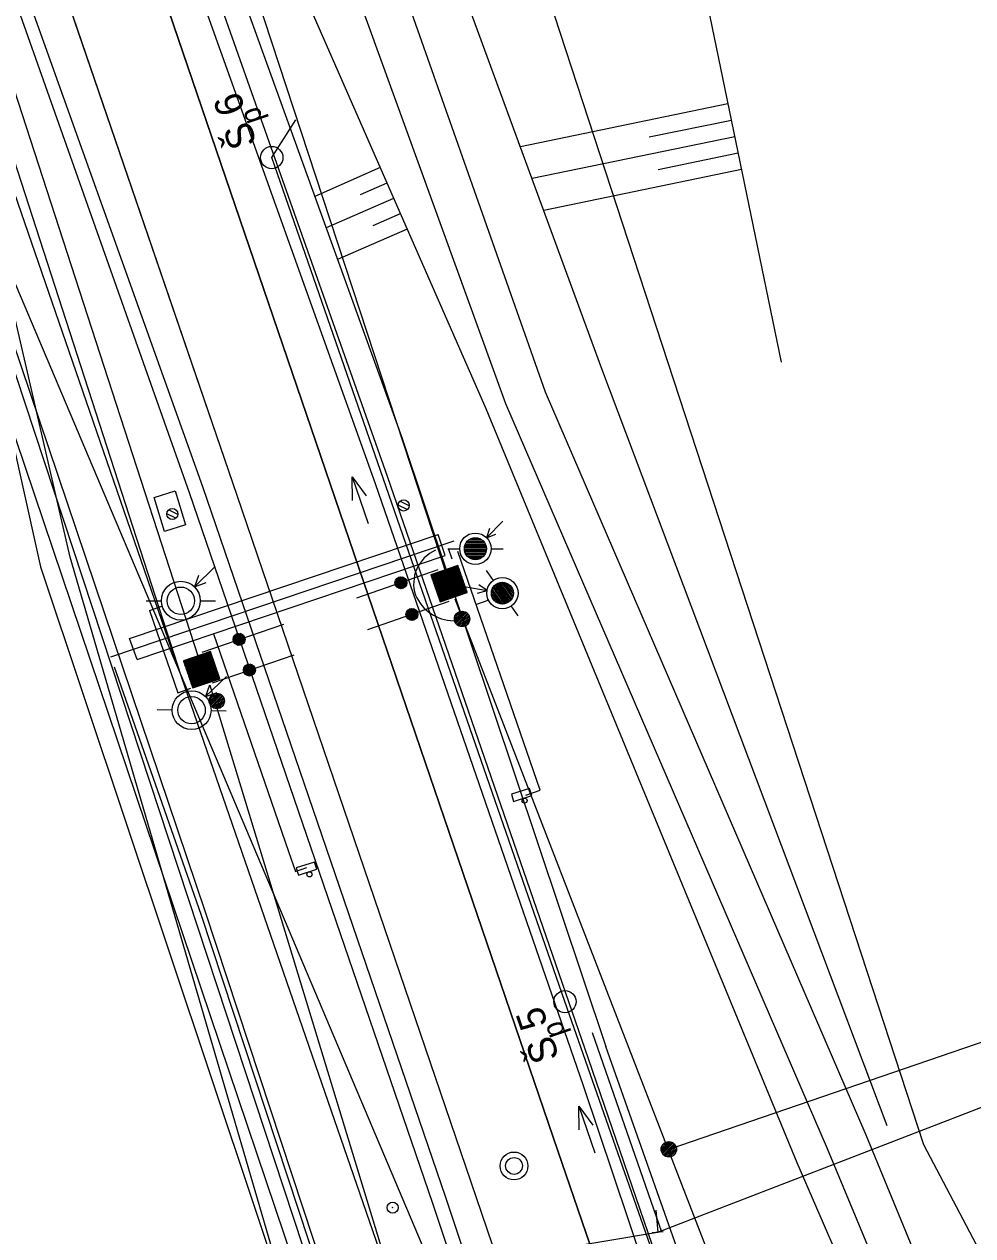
# Model space of a CAD drawing. Extents: x -440566 to -438466, y -1132677 to -1129707.
# Drawn here: x -439341.3 to -439298.8, y -1130686.6 to -1130632.4 of the extents above; entities that cross this region are included whole.
import ezdxf

# ---------------------------------------------------------------- set-up
doc = ezdxf.new("R2010")
doc.units = 0
for name, color, linetype in [('Vrstva 1', 7, 'Continuous'), ('Vrstva 10', 7, 'Continuous'), ('Vrstva 11', 7, 'Continuous'), ('Vrstva 14', 7, 'Continuous'), ('Vrstva 15', 7, 'Continuous'), ('Vrstva 2', 7, 'Continuous'), ('Vrstva 20', 7, 'Continuous'), ('Vrstva 36', 7, 'Continuous'), ('Vrstva 4', 7, 'Continuous'), ('Vrstva 42', 7, 'Continuous'), ('Vrstva 48', 7, 'Continuous'), ('Vrstva 49', 7, 'Continuous'), ('Vrstva 5', 7, 'Continuous'), ('Vrstva 57', 7, 'Continuous'), ('Vrstva 59', 7, 'Continuous'), ('Vrstva 6', 7, 'Continuous'), ('Vrstva 61', 7, 'Continuous'), ('Vrstva 62', 7, 'Continuous'), ('Vrstva 63', 7, 'Continuous'), ('Vrstva 7', 7, 'Continuous'), ('Vrstva 9', 7, 'Continuous')]:
    doc.layers.add(name, color=color, linetype=linetype)

# ---------------------------------------------------------------- blocks, each defined once
blk = doc.blocks.new('KOTV_T')
at = {"layer": 'Vrstva 1'}
for p, q in [((-3.44, -0.33), (0.33, 3.44)), ((-3.42, 0.47), (-0.47, 3.42)), ((-3.31, -0.98), (0.98, 3.31)), ((-3.09, -1.54), (1.54, 3.09)), ((-3.06, 1.61), (-1.61, 3.06)), ((-2.8, -2.02), (2.02, 2.8)), ((-2.44, -2.44), (2.44, 2.44)), ((-2.02, -2.8), (2.8, 2.02)), ((-1.54, -3.09), (3.09, 1.54)), ((-0.98, -3.31), (3.31, 0.98)), ((-0.33, -3.44), (3.44, 0.33)), ((0.47, -3.42), (3.42, -0.47)), ((1.61, -3.06), (3.06, -1.61))]:
    blk.add_line(p, q, dxfattribs=at)
blk.add_circle((0, 0), 3.45, dxfattribs=at)
blk = doc.blocks.new('ST1K_K')
at = {"layer": 'Vrstva 1'}
for p, q in [((0, 0), (45.31, 0)), ((20.84, -3.13), (17.41, 0.3)), ((21.43, -3.01), (17.53, 0.89)), ((21.94, -2.81), (17.73, 1.4)), ((22.38, -2.55), (17.99, 1.84)), ((22.76, -2.22), (18.32, 2.22)), ((23.08, -1.84), (18.7, 2.55)), ((23.35, -1.4), (19.14, 2.81)), ((23.55, -0.89), (19.65, 3.01)), ((23.67, -0.3), (20.24, 3.13)), ((23.65, 0.42), (20.96, 3.11)), ((23.32, 1.46), (22, 2.78)), ((20.12, -3.11), (17.43, -0.42)), ((19.07, -2.78), (17.76, -1.46))]:
    blk.add_line(p, q, dxfattribs=at)
blk.add_circle((20.54, 0), 3.14, dxfattribs=at)
blk = doc.blocks.new('ST_BP')
at = {"layer": 'Vrstva 1'}
for p, q in [((7.5, 7.5), (-7.5, 7.5)), ((-7.5, 7.5), (-7.5, -7.5)), ((-7.5, -7.5), (7.5, 7.5)), ((-7.5, -7.08), (7.08, 7.5)), ((-7.5, -6.65), (6.65, 7.5)), ((-7.5, -6.23), (6.23, 7.5)), ((-7.5, -5.8), (5.8, 7.5)), ((-7.5, -5.38), (5.38, 7.5)), ((-7.5, -4.95), (4.95, 7.5)), ((-7.5, -4.53), (4.53, 7.5)), ((-7.5, -4.11), (4.11, 7.5)), ((-7.5, -3.68), (3.68, 7.5)), ((-7.5, -3.26), (3.26, 7.5)), ((-7.5, -2.83), (2.83, 7.5)), ((-7.5, -2.41), (2.41, 7.5)), ((-7.5, -1.98), (1.98, 7.5)), ((-7.5, -1.56), (1.56, 7.5)), ((-7.5, -1.14), (1.14, 7.5)), ((-7.5, -0.71), (0.71, 7.5)), ((-7.5, -0.29), (0.29, 7.5)), ((-7.5, 0.14), (-0.14, 7.5)), ((-7.5, 0.56), (-0.56, 7.5)), ((-7.5, 0.99), (-0.99, 7.5)), ((-7.5, 1.41), (-1.41, 7.5)), ((-7.5, 1.83), (-1.83, 7.5)), ((-7.5, 2.26), (-2.26, 7.5)), ((-7.5, 2.68), (-2.68, 7.5)), ((-7.5, 3.11), (-3.11, 7.5)), ((-7.5, 3.53), (-3.53, 7.5)), ((-7.5, 3.96), (-3.96, 7.5)), ((-7.5, 4.38), (-4.38, 7.5)), ((-7.5, 4.8), (-4.8, 7.5)), ((-7.5, 5.23), (-5.23, 7.5)), ((-7.5, 5.65), (-5.65, 7.5)), ((-7.5, 6.08), (-6.08, 7.5)), ((-7.5, 6.5), (-6.5, 7.5)), ((-7.5, 6.92), (-6.92, 7.5)), ((-7.5, 7.35), (-7.35, 7.5)), ((-7.08, -7.5), (7.5, 7.08)), ((-6.65, -7.5), (7.5, 6.65)), ((7.5, -7.5), (7.5, 7.5)), ((-6.23, -7.5), (7.5, 6.23)), ((-5.8, -7.5), (7.5, 5.8)), ((-5.38, -7.5), (7.5, 5.38)), ((-4.95, -7.5), (7.5, 4.95)), ((-4.53, -7.5), (7.5, 4.53)), ((-4.11, -7.5), (7.5, 4.11)), ((-3.68, -7.5), (7.5, 3.68)), ((-3.26, -7.5), (7.5, 3.26)), ((-2.83, -7.5), (7.5, 2.83)), ((-2.41, -7.5), (7.5, 2.41)), ((-1.98, -7.5), (7.5, 1.98)), ((-1.56, -7.5), (7.5, 1.56)), ((-1.14, -7.5), (7.5, 1.14)), ((-0.71, -7.5), (7.5, 0.71)), ((-0.29, -7.5), (7.5, 0.29)), ((0.14, -7.5), (7.5, -0.14)), ((0.56, -7.5), (7.5, -0.56)), ((0.99, -7.5), (7.5, -0.99)), ((1.41, -7.5), (7.5, -1.41)), ((1.83, -7.5), (7.5, -1.83)), ((2.26, -7.5), (7.5, -2.26)), ((2.68, -7.5), (7.5, -2.68)), ((3.11, -7.5), (7.5, -3.11)), ((3.53, -7.5), (7.5, -3.53)), ((3.96, -7.5), (7.5, -3.96)), ((4.38, -7.5), (7.5, -4.38)), ((4.8, -7.5), (7.5, -4.8)), ((5.23, -7.5), (7.5, -5.23)), ((5.65, -7.5), (7.5, -5.65)), ((6.08, -7.5), (7.5, -6.08)), ((-7.5, -7.5), (7.5, -7.5)), ((6.5, -7.5), (7.5, -6.5)), ((6.92, -7.5), (7.5, -6.92)), ((7.35, -7.5), (7.5, -7.35))]:
    blk.add_line(p, q, dxfattribs=at)

msp = doc.modelspace()

# ---------------------------------------------------------------- linework, layer by layer
at = {"layer": 'Vrstva 10'}
for p, q in [((-439309.738, -1130635.982), (-439319.036, -1130637.898)), ((-439309.588, -1130636.718), (-439313.262, -1130637.474)), ((-439309.436, -1130637.452), (-439318.514, -1130639.322)), ((-439309.286, -1130638.186), (-439312.872, -1130638.926)), ((-439325.316, -1130638.834), (-439328.242, -1130640.118)), ((-439309.134, -1130638.922), (-439317.992, -1130640.746)), ((-439325.014, -1130639.522), (-439326.204, -1130640.044)), ((-439324.712, -1130640.21), (-439327.732, -1130641.534)), ((-439324.412, -1130640.896), (-439325.636, -1130641.434)), ((-439324.11, -1130641.582), (-439327.22, -1130642.946))]:
    msp.add_line(p, q, dxfattribs=at)
at = {"layer": 'Vrstva 11'}
for points in [[(-439303.556, -1130682.146), (-439317.916, -1130648.878), (-439327.804, -1130620.82), (-439331.376, -1130615.792)], [(-439331.216, -1130618.836), (-439329.76, -1130621.648), (-439319.704, -1130649.398), (-439305.298, -1130682.74)], [(-439290.368, -1130714.13), (-439303.556, -1130682.146)], [(-439305.298, -1130682.74), (-439291.93, -1130714.86)]]:
    msp.add_lwpolyline(points, dxfattribs=at)
at = {"layer": 'Vrstva 14'}
msp.add_lwpolyline([(-439335.44, -1130653.596), (-439334.502, -1130653.304), (-439334.034, -1130654.828), (-439334.97, -1130655.116), (-439335.44, -1130653.596)], dxfattribs=at)
at = {"layer": 'Vrstva 15'}
for p, q in [((-439324.016, -1130653.974), (-439324.432, -1130653.77)), ((-439334.46, -1130654.528), (-439334.87, -1130654.328)), ((-439334.374, -1130654.362), (-439334.79, -1130654.158)), ((-439324.102, -1130654.142), (-439324.512, -1130653.94))]:
    msp.add_line(p, q, dxfattribs=at)
for centre in [(-439324.264, -1130653.954), (-439334.622, -1130654.34)]:
    msp.add_circle(centre, 0.25, dxfattribs=at)
at = {"layer": 'Vrstva 2'}
for centre, radius, start, end in [((-439322.18, -1130657.459), 1.636, 113.691, 198.3072), ((-439322.18, -1130657.459), 1.636, 113.691, 198.3072), ((-439321.987, -1130657.207), 1.907, 203.6959, 268.8931), ((-439321.987, -1130657.207), 1.907, 203.6959, 268.8931)]:
    msp.add_arc(centre, radius, start, end, dxfattribs=at)
at = {"layer": 'Vrstva 20'}
for points in [[(-439321.24, -1130684.25), (-439331.724, -1130653.514), (-439341.682, -1130624.428), (-439343.148, -1130620.102), (-439344.652, -1130615.74), (-439353.044, -1130591.112), (-439364.316, -1130558.138), (-439374.988, -1130526.952), (-439385.508, -1130496.17), (-439396.186, -1130464.956), (-439407.226, -1130432.678), (-439417.232, -1130403.478), (-439427.682, -1130373.028), (-439438.464, -1130341.588), (-439448.942, -1130311.012), (-439450.914, -1130305.246), (-439460.972, -1130277.082), (-439482.918, -1130211.888), (-439494.254, -1130178.768), (-439505.592, -1130145.672), (-439514.996, -1130118.198), (-439526.684, -1130084.16)], [(-439317.356, -1130682.842), (-439326.906, -1130654.872), (-439337.798, -1130622.974), (-439339.224, -1130618.794), (-439340.706, -1130614.468), (-439349.146, -1130589.75), (-439360.302, -1130557.13), (-439371.172, -1130525.358), (-439381.62, -1130494.81), (-439392.342, -1130463.488), (-439403.314, -1130431.488), (-439413.424, -1130401.962), (-439423.826, -1130371.538), (-439434.464, -1130340.548), (-439445.064, -1130309.558), (-439445.462, -1130308.388), (-439447.35, -1130302.89), (-439457.16, -1130275.562), (-439478.968, -1130210.544), (-439490.24, -1130177.636), (-439501.606, -1130144.528), (-439511.068, -1130116.958), (-439519.726, -1130091.71)], [(-439261.504, -1130841.022), (-439269.22, -1130818.812), (-439281.814, -1130783.396), (-439292.526, -1130753.502), (-439304.678, -1130719.318), (-439314.858, -1130690.108), (-439317.356, -1130682.842)], [(-439267.432, -1130843.28), (-439274.97, -1130820.588), (-439286.854, -1130785.132), (-439297.084, -1130755.104), (-439308.786, -1130720.798), (-439319.098, -1130690.52), (-439321.24, -1130684.25)]]:
    msp.add_lwpolyline(points, dxfattribs=at)
at = {"layer": 'Vrstva 36'}
for p, q in [((-439322.55, -1130616.62), (-439300.99, -1130682.56)), ((-439323.66, -1130704.2), (-439346.85, -1130635.55)), ((-439300.99, -1130682.56), (-439292.55, -1130698.49))]:
    msp.add_line(p, q, dxfattribs=at)
at = {"layer": 'Vrstva 4'}
for points in [[(-439316.204, -1130679.942), (-439325.518, -1130652.992), (-439336.244, -1130623.018), (-439338.082, -1130617.638)], [(-439315.982, -1130678.73), (-439324.99, -1130652.666), (-439335.578, -1130622.688), (-439337.526, -1130617.51)], [(-439322.95, -1130685.206), (-439333.858, -1130653.394), (-439343.59, -1130625.92), (-439345.752, -1130619.412)], [(-439322.368, -1130684.93), (-439333.25, -1130653.118), (-439343.108, -1130625.602), (-439345.194, -1130619.284)], [(-439280.01, -1130783.522), (-439290.374, -1130752.75), (-439302.642, -1130717.624), (-439315.982, -1130678.73)], [(-439280.01, -1130783.522), (-439291.102, -1130753.178), (-439303.358, -1130718.188), (-439316.204, -1130679.942)], [(-439237.656, -1130937.666), (-439241.95, -1130926.674), (-439250.188, -1130901.72), (-439259.018, -1130875.526), (-439267.634, -1130849.508), (-439276.91, -1130821.49), (-439290.192, -1130781.67), (-439298.758, -1130756.05), (-439310.466, -1130722.552), (-439322.95, -1130685.206)], [(-439237.656, -1130937.666), (-439241, -1130926.51), (-439249.718, -1130901.172), (-439258.406, -1130875.05), (-439266.76, -1130849.346), (-439276.348, -1130820.732), (-439289.274, -1130782.246), (-439298.276, -1130755.542), (-439309.968, -1130722.042), (-439322.368, -1130684.93)]]:
    msp.add_lwpolyline(points, dxfattribs=at)
at = {"layer": 'Vrstva 42'}
for points in [[(-439395.105, -1130455.427), (-439392.342, -1130463.488), (-439381.62, -1130494.81), (-439371.172, -1130525.358), (-439360.302, -1130557.13), (-439349.146, -1130589.75), (-439340.706, -1130614.468), (-439339.224, -1130618.794), (-439337.798, -1130622.974), (-439326.906, -1130654.872), (-439317.356, -1130682.842)], [(-439321.24, -1130684.25), (-439331.724, -1130653.514), (-439341.682, -1130624.428), (-439343.148, -1130620.102), (-439344.652, -1130615.74), (-439353.044, -1130591.112), (-439364.316, -1130558.138), (-439374.988, -1130526.952), (-439385.508, -1130496.17), (-439396.186, -1130464.956), (-439399.158, -1130456.267)], [(-439317.356, -1130682.842), (-439314.858, -1130690.108), (-439304.678, -1130719.318), (-439294.356, -1130748.353)], [(-439299.143, -1130749.065), (-439308.786, -1130720.798), (-439319.098, -1130690.52), (-439321.24, -1130684.25)]]:
    msp.add_lwpolyline(points, dxfattribs=at)
at = {"layer": 'Vrstva 48'}
msp.add_line((-439330.171, -1130638.383), (-439329.092, -1130636.695), dxfattribs=at)
msp.add_lwpolyline([(-439273.977, -1130800.586), (-439287.398, -1130761.145), (-439303.815, -1130713.917), (-439317.04, -1130676.167), (-439330.171, -1130638.383)], dxfattribs=at)
for centre in [(-439330.171, -1130638.383), (-439317.04, -1130676.167)]:
    msp.add_circle(centre, 0.5, dxfattribs=at)
at = {"layer": 'Vrstva 49'}
for p, q in [((-439326.571, -1130652.681), (-439325.854, -1130654.756)), ((-439316.418, -1130680.852), (-439315.701, -1130682.928))]:
    msp.add_line(p, q, dxfattribs=at)
for points in [[(-439326.552, -1130653.732), (-439326.571, -1130652.681), (-439325.937, -1130653.52)], [(-439316.399, -1130681.904), (-439316.418, -1130680.852), (-439315.785, -1130681.691)]]:
    msp.add_lwpolyline(points, dxfattribs=at)
at = {"layer": 'Vrstva 5'}
msp.add_lwpolyline([(-439277.797, -1130823.31), (-439296.36, -1130772.17), (-439314.646, -1130718.277), (-439334.211, -1130661.631), (-439352.883, -1130603.988)], dxfattribs=at)
at = {"layer": 'Vrstva 57'}
for p, q in [((-439300.573, -1130713.355), (-439321.952, -1130658.15)), ((-439315.693, -1130718.482), (-439332.927, -1130662.012)), ((-439312.411, -1130682.787), (-439281.025, -1130672.03))]:
    msp.add_line(p, q, dxfattribs=at)
at = {"layer": 'Vrstva 59'}
for p, q in [((-439322.958, -1130688.178), (-439346.578, -1130632.414)), ((-439315.822, -1130677.544), (-439312.712, -1130686.468)), ((-439312.712, -1130686.468), (-439322.958, -1130688.178))]:
    msp.add_line(p, q, dxfattribs=at)
msp.add_lwpolyline([(-439240.615, -1130935.08), (-439245.006, -1130936.575), (-439254.477, -1130905.195), (-439274.831, -1130847.058), (-439298.026, -1130780.807), (-439307.773, -1130752.965), (-439314.372, -1130732.153), (-439325.758, -1130696.243), (-439342.929, -1130644.213), (-439353.367, -1130615.721)], dxfattribs=at)
at = {"layer": 'Vrstva 6'}
for p, q in [((-439312.884, -1130686.484), (-439276.288, -1130672.354)), ((-439312.972, -1130685.498), (-439312.884, -1130686.484)), ((-439313.134, -1130686.506), (-439312.636, -1130686.462))]:
    msp.add_line(p, q, dxfattribs=at)
at = {"layer": 'Vrstva 61'}
for p, q in [((-439322.281, -1130657.205), (-439341.23, -1130599.505)), ((-439352.156, -1130603.174), (-439333.292, -1130661.29))]:
    msp.add_line(p, q, dxfattribs=at)
at = {"layer": 'Vrstva 62'}
msp.add_line((-439334.327, -1130661.321), (-439354.141, -1130603.913), dxfattribs=at)
at = {"layer": 'Vrstva 63'}
for p, q in [((-439336.54, -1130659.917), (-439322.722, -1130655.253)), ((-439322.397, -1130656.198), (-439322.722, -1130655.253)), ((-439321.214, -1130655.434), (-439320.886, -1130655.434)), ((-439337.379, -1130660.728), (-439322, -1130655.537)), ((-439322.094, -1130656.36), (-439322.257, -1130655.887)), ((-439321.541, -1130655.893), (-439320.558, -1130655.893)), ((-439321.525, -1130655.827), (-439320.575, -1130655.827)), ((-439321.525, -1130655.958), (-439320.575, -1130655.958)), ((-439321.509, -1130655.761), (-439320.591, -1130655.761)), ((-439321.492, -1130655.696), (-439320.608, -1130655.696)), ((-439321.46, -1130655.63), (-439320.64, -1130655.63)), ((-439321.41, -1130655.565), (-439320.689, -1130655.565)), ((-439321.328, -1130655.499), (-439320.771, -1130655.499)), ((-439336.192, -1130660.855), (-439322.397, -1130656.198)), ((-439318.154, -1130666.701), (-439321.84, -1130656.011)), ((-439321.509, -1130656.024), (-439320.591, -1130656.024)), ((-439321.492, -1130656.089), (-439320.608, -1130656.089)), ((-439321.46, -1130656.155), (-439320.64, -1130656.155)), ((-439321.41, -1130656.22), (-439320.689, -1130656.22)), ((-439321.328, -1130656.286), (-439320.771, -1130656.286)), ((-439321.214, -1130656.351), (-439320.886, -1130656.351)), ((-439319.687, -1130658.332), (-439320.214, -1130657.581)), ((-439319.624, -1130658.308), (-439320.169, -1130657.53)), ((-439319.561, -1130658.284), (-439320.125, -1130657.479)), ((-439319.517, -1130658.233), (-439320.062, -1130657.455)), ((-439319.473, -1130658.182), (-439319.999, -1130657.431)), ((-439319.428, -1130658.131), (-439319.936, -1130657.406)), ((-439319.394, -1130658.067), (-439319.863, -1130657.396)), ((-439319.368, -1130657.989), (-439319.782, -1130657.398)), ((-439319.361, -1130657.884), (-439319.681, -1130657.428)), ((-439319.373, -1130657.753), (-439319.561, -1130657.484)), ((-439320.006, -1130658.335), (-439320.325, -1130657.879)), ((-439319.905, -1130658.365), (-439320.318, -1130657.774)), ((-439320.125, -1130658.279), (-439320.313, -1130658.01)), ((-439319.823, -1130658.367), (-439320.293, -1130657.696)), ((-439319.751, -1130658.357), (-439320.258, -1130657.632)), ((-439335.649, -1130658.654), (-439335.093, -1130658.462)), ((-439321.029, -1130658.386), (-439320.434, -1130658.181)), ((-439336.192, -1130660.855), (-439336.54, -1130659.917)), ((-439334.379, -1130662.341), (-439333.793, -1130662.139)), ((-439318.797, -1130666.923), (-439318.154, -1130666.701))]:
    msp.add_line(p, q, dxfattribs=at)
for points in [[(-439279.55, -1130829.627), (-439292.524, -1130791.32), (-439307.367, -1130752.78), (-439315.541, -1130727.251), (-439322.482, -1130704.449), (-439333.14, -1130672.167), (-439347.586, -1130629.381), (-439352.159, -1130615.872), (-439360.579, -1130591.518), (-439378.343, -1130536.883)], [(-439319.821, -1130654.664), (-439320.557, -1130655.399)], [(-439320.421, -1130654.983), (-439320.557, -1130655.399)], [(-439320.557, -1130655.399), (-439320.141, -1130655.244)], [(-439322.289, -1130655.893), (-439321.746, -1130655.893)], [(-439320.354, -1130655.893), (-439319.811, -1130655.893)], [(-439332.705, -1130656.685), (-439333.625, -1130657.605)], [(-439320.243, -1130657.311), (-439320.554, -1130656.867)], [(-439333.455, -1130657.084), (-439333.625, -1130657.605)], [(-439333.625, -1130657.605), (-439333.105, -1130657.41)], [(-439321.555, -1130657.58), (-439320.53, -1130657.76)], [(-439320.53, -1130657.76), (-439320.896, -1130657.509)], [(-439320.949, -1130657.888), (-439320.53, -1130657.76)], [(-439335.79, -1130658.221), (-439335.112, -1130658.221)], [(-439335.649, -1130658.654), (-439334.379, -1130662.341)], [(-439333.371, -1130658.221), (-439332.693, -1130658.221)], [(-439319.133, -1130658.896), (-439319.444, -1130658.452)], [(-439332.774, -1130659.701), (-439329.416, -1130669.439), (-439329.105, -1130670.34), (-439328.594, -1130670.164)], [(-439229.706, -1130961.083), (-439234.319, -1130947.462), (-439238.472, -1130936.844), (-439247.924, -1130921.561), (-439263.264, -1130880.523), (-439279.451, -1130829.598), (-439292.591, -1130791.38), (-439307.551, -1130752.883), (-439315.726, -1130727.354), (-439322.667, -1130704.552), (-439333.324, -1130672.27), (-439337.219, -1130661.201)], [(-439332.196, -1130661.609), (-439333.132, -1130662.512)], [(-439332.953, -1130661.995), (-439333.132, -1130662.512)], [(-439333.132, -1130662.512), (-439332.608, -1130662.327)], [(-439335.307, -1130663.091), (-439334.629, -1130663.103)], [(-439332.889, -1130663.133), (-439332.211, -1130663.145)]]:
    msp.add_lwpolyline(points, dxfattribs=at)
for points in [[(-439319.338, -1130667.202), (-439318.524, -1130666.942), (-439318.626, -1130666.622), (-439319.44, -1130666.882)], [(-439328.971, -1130670.503), (-439328.157, -1130670.243), (-439328.259, -1130669.923), (-439329.073, -1130670.182)]]:
    msp.add_lwpolyline(points, close=True, dxfattribs=at)
for centre, radius in [((-439321.05, -1130655.893), 0.701), ((-439321.05, -1130655.893), 0.492), ((-439334.241, -1130658.221), 0.87), ((-439334.241, -1130658.221), 0.614), ((-439319.843, -1130657.882), 0.701), ((-439319.843, -1130657.882), 0.492), ((-439333.759, -1130663.118), 0.87), ((-439333.759, -1130663.118), 0.614), ((-439318.848, -1130667.167), 0.114), ((-439328.481, -1130670.468), 0.114)]:
    msp.add_circle(centre, radius, dxfattribs=at)
at = {"layer": 'Vrstva 7'}
msp.add_line((-439324.748, -1130685.414), (-439324.764, -1130685.366), dxfattribs=at)
for centre, radius in [((-439319.32, -1130683.522), 0.623), ((-439319.32, -1130683.522), 0.376), ((-439324.757, -1130685.39), 0.25)]:
    msp.add_circle(centre, radius, dxfattribs=at)
at = {"layer": 'Vrstva 9'}
for points in [[(-439302.616, -1130681.722), (-439315.394, -1130647.836), (-439325.592, -1130620.022), (-439330.646, -1130613.072), (-439326.982, -1130606.17), (-439310.098, -1130596.386)], [(-439304.064, -1130603.548), (-439312.168, -1130612.528), (-439313.262, -1130618.886), (-439307.358, -1130647.542)], [(-439337.526, -1130617.51), (-439334.41, -1130623.048), (-439324.342, -1130650.912), (-439315.202, -1130678.168)], [(-439337.526, -1130617.51), (-439332.438, -1130622.598), (-439320.59, -1130649.608), (-439306.658, -1130683.374)], [(-439329.016, -1130691.134), (-439339.192, -1130656.276), (-439343.888, -1130636.026), (-439354.284, -1130638.834)], [(-439353.788, -1130640.606), (-439344.68, -1130638.07), (-439340.524, -1130656.706), (-439329.016, -1130691.134)], [(-439225.732, -1130933.398), (-439229.604, -1130923.888), (-439239.092, -1130898.916), (-439247.79, -1130873.56), (-439257.606, -1130845.04), (-439266.65, -1130817.146), (-439278.574, -1130785.616), (-439289.83, -1130752.464), (-439300.562, -1130719.612), (-439315.202, -1130678.168)], [(-439306.658, -1130683.374), (-439292.824, -1130715.24)]]:
    msp.add_lwpolyline(points, dxfattribs=at)

# ---------------------------------------------------------------- block references
at = {"layer": 'Vrstva 2'}
for name, p, xscale, yscale, rotation in [('ST1K_K', (-439322.729, -1130656.839), 0.08533299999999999, 0.08533300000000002, -160.83699069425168), ('ST1K_K', (-439322.729, -1130656.839), 0.08533299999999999, 0.08533300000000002, -160.83699069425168), ('ST_BP', (-439322.236, -1130657.456), 0.085333, 0.08533300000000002, -160.83370949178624), ('ST_BP', (-439322.236, -1130657.456), 0.085333, 0.08533300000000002, -160.83370949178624), ('ST1K_K', (-439322.236, -1130658.256), 0.08533300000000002, 0.08533300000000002, -160.83037784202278), ('ST1K_K', (-439322.236, -1130658.256), 0.08533300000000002, 0.08533300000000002, -160.83037784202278), ('ST1K_K', (-439333.289, -1130660.521), 0.08533300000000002, 0.085333, 18.917487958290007), ('ST1K_K', (-439333.289, -1130660.521), 0.08533300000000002, 0.085333, 18.917487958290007), ('ST_BP', (-439333.305, -1130661.313), 0.085333, 0.085333, 18.91748967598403), ('ST_BP', (-439333.305, -1130661.313), 0.085333, 0.085333, 18.91748967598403), ('ST1K_K', (-439332.829, -1130661.893), 0.085333, 0.08533300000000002, 18.91748795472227), ('ST1K_K', (-439332.829, -1130661.893), 0.085333, 0.08533300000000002, 18.91748795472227)]:
    msp.add_blockref(name, p, dxfattribs=dict(at, xscale=xscale, yscale=yscale, rotation=rotation))
at = {"layer": 'Vrstva 57', "xscale": 0.10000000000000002, "yscale": 0.1, "rotation": 1}
for p in [(-439321.647, -1130659.036), (-439332.632, -1130662.706), (-439312.389, -1130682.777)]:
    msp.add_blockref('KOTV_T', p, dxfattribs=at)

# ---------------------------------------------------------------- texts
at = {"layer": 'Vrstva 49'}
for s, height, p in [('Š 6', 1.25, (-439330.824, -1130637.745)), ('p', 0.938, (-439330.545, -1130636.703)), ('Š 5', 1.25, (-439317.278, -1130678.664)), ('p', 0.938, (-439316.999, -1130677.622))]:
    msp.add_text(s, height=height, rotation=108.9175, dxfattribs=at).set_placement(p)

doc.saveas('drawing.dxf')
